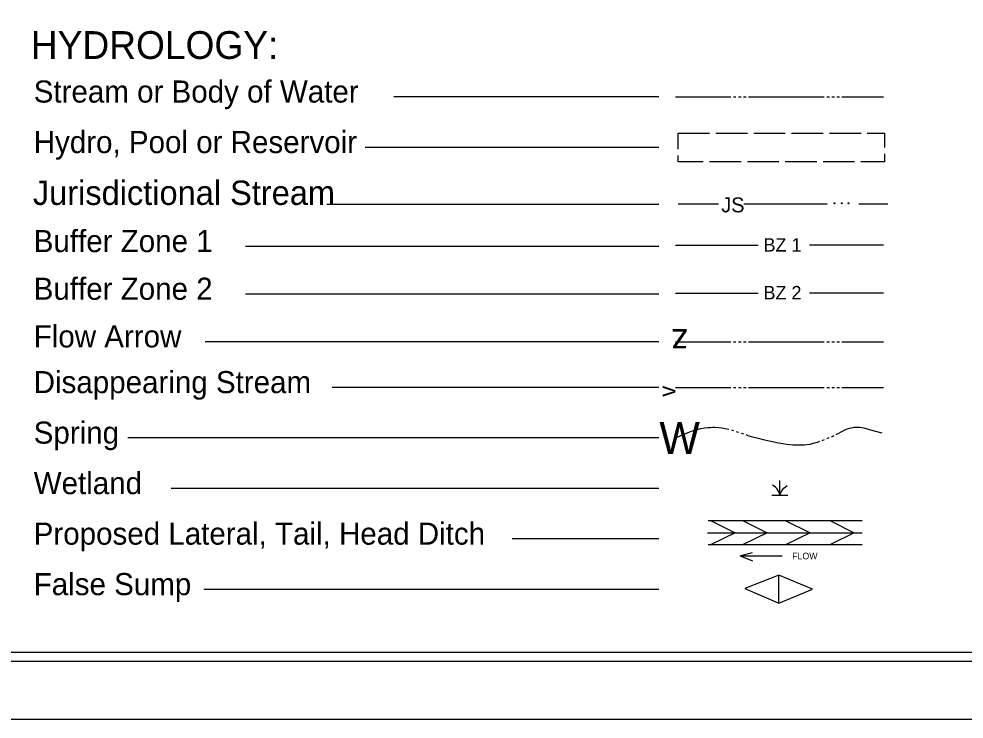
# Model space of a CAD drawing. Extents: x 2594871.4 to 2594905.1, y 784137.6 to 784159.6.
# Drawn here: x 2594875.28 to 2594882.63, y 784137.56 to 784143 of the extents above; entities that cross this region are included whole.
import ezdxf

# ---------------------------------------------------------------- set-up
doc = ezdxf.new("R2010")
doc.units = 0
for name, color, linetype in [('Default', 7, 'Continuous'), ('Sheet Plot Border Inside CELL', 7, 'Continuous'), ('Sheet Plot Border Outside CELL', 7, 'Continuous'), ('Sheet Symbology CELL', 7, 'Continuous')]:
    doc.layers.add(name, color=color, linetype=linetype)

msp = doc.modelspace()

# ---------------------------------------------------------------- linework, layer by layer
at = {"layer": 'Default'}
for p, q in [((2594880.2538, 784142.3951), (2594878.1942, 784142.3951)), ((2594880.3816, 784142.3951), (2594880.8136, 784142.3951)), ((2594880.8332, 784142.3951), (2594880.8528, 784142.3951)), ((2594880.8724, 784142.3951), (2594880.8921, 784142.3951)), ((2594880.9117, 784142.3951), (2594880.9313, 784142.3951)), ((2594880.9509, 784142.3951), (2594881.5394, 784142.3951)), ((2594881.559, 784142.3951), (2594881.5786, 784142.3951)), ((2594881.5982, 784142.3951), (2594881.6178, 784142.3951)), ((2594881.6375, 784142.3951), (2594881.6571, 784142.3951)), ((2594881.6767, 784142.3951), (2594881.9998, 784142.3951)), ((2594880.4024, 784142.1121), (2594880.6476, 784142.1121)), ((2594880.4024, 784141.9885), (2594880.4024, 784142.1121)), ((2594880.6966, 784142.1121), (2594880.9418, 784142.1121)), ((2594880.9909, 784142.1121), (2594881.2361, 784142.1121)), ((2594881.2851, 784142.1121), (2594881.5303, 784142.1121)), ((2594881.5793, 784142.1121), (2594881.8245, 784142.1121)), ((2594880.2538, 784142.0027), (2594877.9708, 784142.0027)), ((2594880.8923, 784141.89), (2594880.6471, 784141.89)), ((2594881.1865, 784141.89), (2594880.9413, 784141.89)), ((2594881.4808, 784141.89), (2594881.2356, 784141.89)), ((2594881.775, 784141.89), (2594881.5298, 784141.89)), ((2594880.2538, 784141.5595), (2594877.6723, 784141.5595)), ((2594880.2538, 784141.2336), (2594877.0417, 784141.2336)), ((2594880.3816, 784141.2421), (2594881.0249, 784141.2421)), ((2594881.9998, 784141.2421), (2594881.425, 784141.2421)), ((2594880.2538, 784140.8634), (2594877.0417, 784140.8634)), ((2594880.3816, 784140.8698), (2594881.0249, 784140.8698)), ((2594881.9998, 784140.8698), (2594881.425, 784140.8698)), ((2594880.2538, 784140.4933), (2594876.7262, 784140.4933)), ((2594880.3816, 784140.4933), (2594880.8136, 784140.4933)), ((2594880.8332, 784140.4933), (2594880.8528, 784140.4933)), ((2594880.8724, 784140.4933), (2594880.8921, 784140.4933)), ((2594880.9117, 784140.4933), (2594880.9313, 784140.4933)), ((2594880.9509, 784140.4933), (2594881.5394, 784140.4933)), ((2594881.559, 784140.4933), (2594881.5786, 784140.4933)), ((2594881.5982, 784140.4933), (2594881.6178, 784140.4933)), ((2594881.6375, 784140.4933), (2594881.6571, 784140.4933)), ((2594881.6767, 784140.4933), (2594881.9998, 784140.4933)), ((2594880.2538, 784140.1379), (2594877.7134, 784140.1379)), ((2594880.3816, 784140.1379), (2594880.8136, 784140.1379)), ((2594880.8332, 784140.1379), (2594880.8528, 784140.1379)), ((2594880.8724, 784140.1379), (2594880.8921, 784140.1379)), ((2594880.9117, 784140.1379), (2594880.9313, 784140.1379)), ((2594880.9509, 784140.1379), (2594881.5394, 784140.1379)), ((2594881.559, 784140.1379), (2594881.5786, 784140.1379)), ((2594881.5982, 784140.1379), (2594881.6178, 784140.1379)), ((2594881.6375, 784140.1379), (2594881.6571, 784140.1379)), ((2594881.6767, 784140.1379), (2594881.9998, 784140.1379)), ((2594880.2538, 784139.7456), (2594876.1253, 784139.7456)), ((2594880.8918, 784139.7838), (2594880.9105, 784139.7774)), ((2594881.5234, 784139.7264), (2594881.5416, 784139.7338)), ((2594881.56, 784139.7409), (2594881.5779, 784139.7485)), ((2594881.1929, 784139.3001), (2594881.1929, 784139.4153)), ((2594880.2538, 784139.3533), (2594876.4639, 784139.3533)), ((2594881.1309, 784139.3001), (2594881.2559, 784139.3001)), ((2594880.6361, 784139.1032), (2594881.8329, 784139.1032)), ((2594880.6537, 784139.1032), (2594880.8457, 784139.009)), ((2594880.9031, 784139.1032), (2594881.0951, 784139.009)), ((2594881.2356, 784139.1032), (2594881.4283, 784139.009)), ((2594881.5835, 784139.1032), (2594881.7718, 784139.009)), ((2594880.6309, 784139.009), (2594881.8329, 784139.009)), ((2594880.8457, 784139.009), (2594880.6591, 784138.9178)), ((2594881.0951, 784139.009), (2594880.9092, 784138.9178)), ((2594881.4283, 784139.009), (2594881.2424, 784138.9178)), ((2594881.7718, 784139.009), (2594881.5887, 784138.9178)), ((2594880.2538, 784138.961), (2594879.1127, 784138.961)), ((2594880.6361, 784138.9178), (2594881.8329, 784138.9178)), ((2594880.8862, 784138.8295), (2594880.9803, 784138.856)), ((2594880.8862, 784138.8295), (2594881.2128, 784138.8295)), ((2594880.8862, 784138.8295), (2594880.9803, 784138.7913)), ((2594881.1865, 784138.6787), (2594880.9203, 784138.5753)), ((2594881.1865, 784138.462), (2594881.1865, 784138.6787)), ((2594881.4477, 784138.5704), (2594881.1865, 784138.6787)), ((2594880.2538, 784138.5686), (2594876.7177, 784138.5686)), ((2594880.9203, 784138.5753), (2594881.1865, 784138.462)), ((2594881.1865, 784138.462), (2594881.4477, 784138.5704))]:
    msp.add_line(p, q, dxfattribs=at)
for points in [[(2594881.8736, 784142.1121), (2594882.0074, 784142.1121), (2594882.0074, 784142.0008)], [(2594880.5981, 784141.89), (2594880.4024, 784141.89), (2594880.4024, 784141.9395)], [(2594882.0074, 784141.9517), (2594882.0074, 784141.89), (2594881.824, 784141.89)], [(2594880.4024, 784141.5634), (2594880.7164, 784141.5634)], [(2594880.9133, 784141.5634), (2594881.1884, 784141.5634)], [(2594881.1884, 784141.5634), (2594881.561, 784141.5634)], [(2594881.8081, 784141.5634), (2594882.0321, 784141.5634)], [(2594880.3818, 784139.7456), (2594880.4375, 784139.7689), (2594880.4934, 784139.7924), (2594880.5074, 784139.7978), (2594880.5321, 784139.8064), (2594880.5512, 784139.8115), (2594880.5799, 784139.8182), (2594880.6089, 784139.8233), (2594880.6331, 784139.8262), (2594880.6547, 784139.828), (2594880.6736, 784139.8284), (2594880.6903, 784139.8284), (2594880.7194, 784139.8267), (2594880.7413, 784139.8245), (2594880.7575, 784139.8221), (2594880.7817, 784139.8174), (2594880.7984, 784139.8135)], [(2594880.8175, 784139.8083), (2594880.8266, 784139.8056), (2594880.8362, 784139.8027)], [(2594881.6316, 784139.773), (2594881.6409, 784139.7777), (2594881.6794, 784139.7978), (2594881.699, 784139.8074), (2594881.7193, 784139.8157), (2594881.7348, 784139.8208), (2594881.7485, 784139.8243), (2594881.7608, 784139.8267), (2594881.7716, 784139.8284), (2594881.7907, 784139.8297), (2594881.8049, 784139.8297), (2594881.8155, 784139.8289), (2594881.8312, 784139.8267), (2594881.8466, 784139.8233), (2594881.9162, 784139.8042), (2594881.9856, 784139.7848)], [(2594880.8548, 784139.7966), (2594880.8629, 784139.7939), (2594880.8734, 784139.7902)], [(2594880.9291, 784139.7711), (2594880.944, 784139.7659), (2594880.9715, 784139.7578), (2594881.0242, 784139.7439), (2594881.0639, 784139.7338), (2594881.1235, 784139.7201), (2594881.1836, 784139.7076), (2594881.2169, 784139.7017), (2594881.2464, 784139.6973), (2594881.2724, 784139.6943), (2594881.2952, 784139.6924), (2594881.315, 784139.6914), (2594881.3327, 784139.6909), (2594881.3631, 784139.6914), (2594881.3859, 784139.6929), (2594881.403, 784139.6948), (2594881.4283, 784139.6985), (2594881.4533, 784139.7039), (2594881.4722, 784139.709), (2594881.4886, 784139.7139), (2594881.505, 784139.7198)], [(2594881.596, 784139.7561), (2594881.5999, 784139.7578), (2594881.6139, 784139.7642)], [(2594881.1929, 784139.3001), (2594881.19, 784139.3139), (2594881.186, 784139.3277), (2594881.1791, 784139.3405), (2594881.1703, 784139.3523), (2594881.1605, 784139.3631), (2594881.1486, 784139.371), (2594881.1358, 784139.3779)], [(2594881.1929, 784139.3001), (2594881.1988, 784139.3149), (2594881.2057, 784139.3296), (2594881.2146, 784139.3434), (2594881.2254, 784139.3552), (2594881.2372, 784139.3661), (2594881.25, 784139.3759)]]:
    msp.add_lwpolyline(points, dxfattribs=at)
for centre in [(2594881.6187, 784141.5688), (2594881.6767, 784141.5688), (2594881.7274, 784141.5688)]:
    msp.add_ellipse(centre, major_axis=(0, 0.00386), ratio=0.938496, dxfattribs=at)
at = {"layer": 'Sheet Plot Border Inside CELL'}
msp.add_lwpolyline([(2594871.6321, 784138.0107), (2594904.9621, 784138.0107), (2594904.9621, 784159.1127), (2594871.6321, 784159.1127)], close=True, dxfattribs=at)
at = {"layer": 'Sheet Plot Border Outside CELL'}
msp.add_lwpolyline([(2594905.0521, 784159.5617), (2594871.3721, 784159.5617), (2594871.3721, 784137.5617), (2594905.0521, 784137.5617)], close=True, dxfattribs=at)
at = {"layer": 'Sheet Symbology CELL'}
msp.add_lwpolyline([(2594904.7121, 784159.0617), (2594874.7121, 784159.0617), (2594874.7121, 784138.0821), (2594904.7121, 784138.0821)], close=True, dxfattribs=at)

# ---------------------------------------------------------------- texts
at = {"layer": 'Default'}
for s, height, rotation, p in [('HYDROLOGY:', 0.21577, 360, (2594875.372, 784142.6898)), ('Stream or Body of Water', 0.171636, 360, (2594875.3943, 784142.3507)), ('Hydro, Pool or Reservoir', 0.171636, 360, (2594875.3943, 784141.9584)), ('Jurisdictional Stream', 0.189211, 360, (2594875.3878, 784141.5556)), ('JS', 0.11584, 360, (2594880.7382, 784141.4982)), ('Buffer Zone 1', 0.171636, 360, (2594875.3943, 784141.1892)), ('BZ 1', 0.10426, 360, (2594881.067, 784141.1929)), ('Buffer Zone 2', 0.171636, 360, (2594875.3943, 784140.819)), ('BZ 2', 0.10426, 360, (2594881.067, 784140.8221)), ('Flow Arrow', 0.17164, 360, (2594875.3943, 784140.4489)), ('z', 0.1962, 180.00002, (2594880.4799, 784140.5913)), ('Disappearing Stream', 0.171636, 360, (2594875.3943, 784140.0935)), ('v', 0.1295, 89.75915, (2594880.3816, 784140.0646)), ('Spring', 0.17164, 360, (2594875.3943, 784139.7012)), ('W', 0.2501, 360, (2594880.2568, 784139.6205)), ('Wetland', 0.17164, 360, (2594875.3943, 784139.3089)), ('Proposed Lateral, Tail, Head Ditch', 0.171636, 360, (2594875.3943, 784138.9166)), ('FLOW', 0.05086, 360, (2594881.29, 784138.8031)), ('False Sump', 0.17164, 360, (2594875.3943, 784138.5243))]:
    msp.add_text(s, height=height, rotation=rotation, dxfattribs=at).set_placement(p)

doc.saveas('drawing.dxf')
